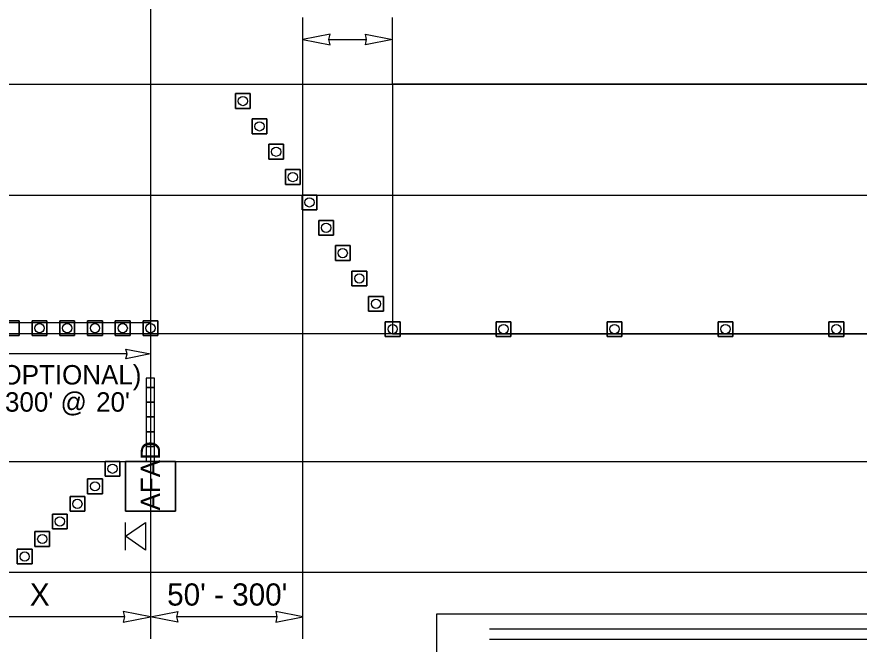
# Model space of a CAD drawing. Extents: x 99999.1 to 100095.7, y 99995 to 100010.7.
# Drawn here: x 100003.795 to 100006.832, y 100005.473 to 100007.734 of the extents above; entities that cross this region are included whole.
import ezdxf

# ---------------------------------------------------------------- set-up
doc = ezdxf.new("R2010")
doc.units = 0
for name, color, linetype in [('RD_ED_ShoulderPavedEdge', 7, 'Continuous'), ('RD_MK_LineDblYellowCenter', 7, 'Continuous'), ('RD_MK_LineEdgeWhite', 7, 'Continuous'), ('RD_MK_LineNoPass', 7, 'Continuous'), ('RD_MK_LineSkipCenter', 7, 'Continuous'), ('TR_WZ_AFAD', 7, 'Continuous'), ('TR_WZ_PortableSignMountBlk-Wht', 7, 'Continuous'), ('TR_WZ_TrafficCone', 7, 'Continuous'), ('TR_WZ_WorkZoneDetails', 7, 'Continuous'), ('TR_WZ_WorkZoneTextCurrent', 7, 'Continuous')]:
    doc.layers.add(name, color=color, linetype=linetype)

msp = doc.modelspace()

# ---------------------------------------------------------------- linework, layer by layer
at = {"layer": 'RD_ED_ShoulderPavedEdge'}
for p, q in [((100000.1076, 100007.4923), (100015.6424, 100007.4923)), ((100000.1076, 100005.7323), (100015.6424, 100005.7323))]:
    msp.add_line(p, q, dxfattribs=at)
at = {"layer": 'RD_MK_LineDblYellowCenter'}
for p, q in [((100005.4994, 100005.5286), (100008.0081, 100005.5286)), ((100005.4994, 100005.4911), (100008.0081, 100005.4911))]:
    msp.add_line(p, q, dxfattribs=at)
at = {"layer": 'RD_MK_LineEdgeWhite'}
for p, q in [((100000.1076, 100007.0923), (100015.6424, 100007.0923)), ((100000.1076, 100006.1323), (100015.6424, 100006.1323))]:
    msp.add_line(p, q, dxfattribs=at)
at = {"layer": 'RD_MK_LineNoPass'}
msp.add_line((100003.4767, 100006.6323), (100004.2767, 100006.6323), dxfattribs=at)
at = {"layer": 'RD_MK_LineSkipCenter'}
msp.add_lwpolyline([(100011.15, 100006.5923), (100003.4767, 100006.5923)], dxfattribs=at)
at = {"layer": 'TR_WZ_AFAD'}
for p, q in [((100004.2916, 100006.399), (100004.2916, 100006.4323)), ((100004.2616, 100006.399), (100004.2616, 100006.3457)), ((100004.2616, 100006.399), (100004.2766, 100006.399)), ((100004.2766, 100006.399), (100004.2916, 100006.399)), ((100004.2916, 100006.3457), (100004.2916, 100006.399)), ((100004.2616, 100006.3457), (100004.2616, 100006.2923)), ((100004.2766, 100006.3457), (100004.2616, 100006.3457)), ((100004.2916, 100006.3457), (100004.2766, 100006.3457)), ((100004.2916, 100006.2923), (100004.2916, 100006.3457)), ((100004.2616, 100006.2923), (100004.2616, 100006.239)), ((100004.2616, 100006.2923), (100004.2766, 100006.2923)), ((100004.2766, 100006.2923), (100004.2916, 100006.2923)), ((100004.2916, 100006.239), (100004.2916, 100006.2923)), ((100004.2766, 100006.239), (100004.2616, 100006.239)), ((100004.2616, 100006.239), (100004.2616, 100006.1857)), ((100004.2916, 100006.239), (100004.2766, 100006.239)), ((100004.2916, 100006.1857), (100004.2916, 100006.239)), ((100004.2616, 100006.1857), (100004.2616, 100006.1323)), ((100004.1866, 100005.9523), (100004.1866, 100006.1323)), ((100004.1866, 100006.1323), (100004.3666, 100006.1323)), ((100004.27, 100006.1323), (100004.1866, 100006.1323)), ((100004.1866, 100006.1323), (100004.1866, 100005.9523)), ((100004.2616, 100006.1323), (100004.27, 100006.1323)), ((100004.27, 100006.1323), (100004.2766, 100006.1323)), ((100004.3666, 100006.1323), (100004.3666, 100005.9523)), ((100004.3666, 100005.9523), (100004.3666, 100006.1323)), ((100004.3666, 100005.9523), (100004.1866, 100005.9523)), ((100004.1866, 100005.9523), (100004.3666, 100005.9523))]:
    msp.add_line(p, q, dxfattribs=at)
for points in [[(100004.2916, 100006.4323), (100004.2616, 100006.4323), (100004.2616, 100006.399)], [(100004.2916, 100006.1323), (100004.2916, 100006.4323), (100004.2616, 100006.4323), (100004.2616, 100006.1323)], [(100004.2916, 100006.399), (100004.2766, 100006.399), (100004.2616, 100006.399)], [(100004.2616, 100006.3457), (100004.2766, 100006.3457), (100004.2916, 100006.3457)], [(100004.2916, 100006.2923), (100004.2766, 100006.2923), (100004.2616, 100006.2923)], [(100004.2616, 100006.239), (100004.2766, 100006.239), (100004.2916, 100006.239)], [(100004.2916, 100006.1857), (100004.2766, 100006.1857), (100004.2616, 100006.1857)], [(100004.2616, 100006.1857), (100004.2766, 100006.1857), (100004.2916, 100006.1857)], [(100004.2766, 100006.1323), (100004.2833, 100006.1323), (100004.2916, 100006.1323), (100004.2916, 100006.1857)], [(100004.3666, 100006.1323), (100004.2833, 100006.1323), (100004.27, 100006.1323)]]:
    msp.add_lwpolyline(points, dxfattribs=at)
at = {"layer": 'TR_WZ_PortableSignMountBlk-Wht'}
msp.add_line((100004.1867, 100005.8123), (100004.1867, 100005.9123), dxfattribs=at)
msp.add_lwpolyline([(100004.1867, 100005.8622), (100004.2585, 100005.9123), (100004.2585, 100005.8123)], close=True, dxfattribs=at)
at = {"layer": 'TR_WZ_TrafficCone'}
for points in [[(100004.6367, 100007.4577), (100004.5834, 100007.4577), (100004.5834, 100007.4043), (100004.6367, 100007.4043), (100004.6367, 100007.4577)], [(100004.6367, 100007.4043), (100004.5834, 100007.4043), (100004.5834, 100007.4577), (100004.6367, 100007.4577), (100004.6367, 100007.4043)], [(100004.6967, 100007.3663), (100004.6434, 100007.3663), (100004.6434, 100007.313), (100004.6967, 100007.313), (100004.6967, 100007.3663)], [(100004.6967, 100007.313), (100004.6434, 100007.313), (100004.6434, 100007.3663), (100004.6967, 100007.3663), (100004.6967, 100007.313)], [(100004.7567, 100007.275), (100004.7034, 100007.275), (100004.7034, 100007.2217), (100004.7567, 100007.2217), (100004.7567, 100007.275)], [(100004.7567, 100007.2217), (100004.7034, 100007.2217), (100004.7034, 100007.275), (100004.7567, 100007.275), (100004.7567, 100007.2217)], [(100004.8167, 100007.1837), (100004.7634, 100007.1837), (100004.7634, 100007.1303), (100004.8167, 100007.1303), (100004.8167, 100007.1837)], [(100004.8167, 100007.1303), (100004.7634, 100007.1303), (100004.7634, 100007.1837), (100004.8167, 100007.1837), (100004.8167, 100007.1303)], [(100004.8234, 100007.0923), (100004.8767, 100007.0923), (100004.8767, 100007.039), (100004.8234, 100007.039), (100004.8234, 100007.0923)], [(100004.8234, 100007.039), (100004.8767, 100007.039), (100004.8767, 100007.0923), (100004.8234, 100007.0923), (100004.8234, 100007.039)], [(100004.8834, 100007.001), (100004.9367, 100007.001), (100004.9367, 100006.9477), (100004.8834, 100006.9477), (100004.8834, 100007.001)], [(100004.8834, 100006.9477), (100004.9367, 100006.9477), (100004.9367, 100007.001), (100004.8834, 100007.001), (100004.8834, 100006.9477)], [(100004.9434, 100006.9097), (100004.9967, 100006.9097), (100004.9967, 100006.8563), (100004.9434, 100006.8563), (100004.9434, 100006.9097)], [(100004.9434, 100006.8563), (100004.9967, 100006.8563), (100004.9967, 100006.9097), (100004.9434, 100006.9097), (100004.9434, 100006.8563)], [(100005.0034, 100006.8183), (100005.0567, 100006.8183), (100005.0567, 100006.765), (100005.0034, 100006.765), (100005.0034, 100006.8183)], [(100005.0034, 100006.765), (100005.0567, 100006.765), (100005.0567, 100006.8183), (100005.0034, 100006.8183), (100005.0034, 100006.765)], [(100005.0634, 100006.727), (100005.1167, 100006.727), (100005.1167, 100006.6737), (100005.0634, 100006.6737), (100005.0634, 100006.727)], [(100005.0634, 100006.6737), (100005.1167, 100006.6737), (100005.1167, 100006.727), (100005.0634, 100006.727), (100005.0634, 100006.6737)], [(100003.8033, 100006.639), (100003.75, 100006.639), (100003.75, 100006.5857), (100003.8033, 100006.5857), (100003.8033, 100006.639)], [(100003.8033, 100006.5857), (100003.75, 100006.5857), (100003.75, 100006.639), (100003.8033, 100006.639), (100003.8033, 100006.5857)], [(100003.9033, 100006.639), (100003.85, 100006.639), (100003.85, 100006.5857), (100003.9033, 100006.5857), (100003.9033, 100006.639)], [(100003.9033, 100006.5857), (100003.85, 100006.5857), (100003.85, 100006.639), (100003.9033, 100006.639), (100003.9033, 100006.5857)], [(100004.0033, 100006.639), (100003.95, 100006.639), (100003.95, 100006.5857), (100004.0033, 100006.5857), (100004.0033, 100006.639)], [(100004.0033, 100006.5857), (100003.95, 100006.5857), (100003.95, 100006.639), (100004.0033, 100006.639), (100004.0033, 100006.5857)], [(100004.1033, 100006.639), (100004.05, 100006.639), (100004.05, 100006.5857), (100004.1033, 100006.5857), (100004.1033, 100006.639)], [(100004.1033, 100006.5857), (100004.05, 100006.5857), (100004.05, 100006.639), (100004.1033, 100006.639), (100004.1033, 100006.5857)], [(100004.2033, 100006.639), (100004.15, 100006.639), (100004.15, 100006.5857), (100004.2033, 100006.5857), (100004.2033, 100006.639)], [(100004.2033, 100006.5857), (100004.15, 100006.5857), (100004.15, 100006.639), (100004.2033, 100006.639), (100004.2033, 100006.5857)], [(100004.3033, 100006.639), (100004.25, 100006.639), (100004.25, 100006.5857), (100004.3033, 100006.5857), (100004.3033, 100006.639)], [(100004.3033, 100006.5857), (100004.25, 100006.5857), (100004.25, 100006.639), (100004.3033, 100006.639), (100004.3033, 100006.5857)], [(100005.1234, 100006.6357), (100005.1767, 100006.6357), (100005.1767, 100006.5823), (100005.1234, 100006.5823), (100005.1234, 100006.6357)], [(100005.1234, 100006.5823), (100005.1767, 100006.5823), (100005.1767, 100006.6357), (100005.1234, 100006.6357), (100005.1234, 100006.5823)], [(100005.5234, 100006.6357), (100005.5767, 100006.6357), (100005.5767, 100006.5823), (100005.5234, 100006.5823), (100005.5234, 100006.6357)], [(100005.5234, 100006.5823), (100005.5767, 100006.5823), (100005.5767, 100006.6357), (100005.5234, 100006.6357), (100005.5234, 100006.5823)], [(100005.9234, 100006.6357), (100005.9767, 100006.6357), (100005.9767, 100006.5823), (100005.9234, 100006.5823), (100005.9234, 100006.6357)], [(100005.9234, 100006.5823), (100005.9767, 100006.5823), (100005.9767, 100006.6357), (100005.9234, 100006.6357), (100005.9234, 100006.5823)], [(100006.3234, 100006.6357), (100006.3767, 100006.6357), (100006.3767, 100006.5823), (100006.3234, 100006.5823), (100006.3234, 100006.6357)], [(100006.3234, 100006.5823), (100006.3767, 100006.5823), (100006.3767, 100006.6357), (100006.3234, 100006.6357), (100006.3234, 100006.5823)], [(100006.7234, 100006.6357), (100006.7767, 100006.6357), (100006.7767, 100006.5823), (100006.7234, 100006.5823), (100006.7234, 100006.6357)], [(100006.7234, 100006.5823), (100006.7767, 100006.5823), (100006.7767, 100006.6357), (100006.7234, 100006.6357), (100006.7234, 100006.5823)], [(100004.1133, 100006.1323), (100004.1667, 100006.1323), (100004.1667, 100006.079), (100004.1133, 100006.079), (100004.1133, 100006.1323)], [(100004.1133, 100006.079), (100004.1667, 100006.079), (100004.1667, 100006.1323), (100004.1133, 100006.1323), (100004.1133, 100006.079)], [(100004.05, 100006.069), (100004.1033, 100006.069), (100004.1033, 100006.0157), (100004.05, 100006.0157), (100004.05, 100006.069)], [(100004.05, 100006.0157), (100004.1033, 100006.0157), (100004.1033, 100006.069), (100004.05, 100006.069), (100004.05, 100006.0157)], [(100003.9867, 100006.0057), (100004.04, 100006.0057), (100004.04, 100005.9523), (100003.9867, 100005.9523), (100003.9867, 100006.0057)], [(100003.9867, 100005.9523), (100004.04, 100005.9523), (100004.04, 100006.0057), (100003.9867, 100006.0057), (100003.9867, 100005.9523)], [(100003.9767, 100005.9423), (100003.9233, 100005.9423), (100003.9233, 100005.889), (100003.9767, 100005.889), (100003.9767, 100005.9423)], [(100003.9767, 100005.889), (100003.9233, 100005.889), (100003.9233, 100005.9423), (100003.9767, 100005.9423), (100003.9767, 100005.889)], [(100003.9133, 100005.879), (100003.86, 100005.879), (100003.86, 100005.8257), (100003.9133, 100005.8257), (100003.9133, 100005.879)], [(100003.9133, 100005.8257), (100003.86, 100005.8257), (100003.86, 100005.879), (100003.9133, 100005.879), (100003.9133, 100005.8257)], [(100003.85, 100005.8157), (100003.7967, 100005.8157), (100003.7967, 100005.7623), (100003.85, 100005.7623), (100003.85, 100005.8157)], [(100003.85, 100005.7623), (100003.7967, 100005.7623), (100003.7967, 100005.8157), (100003.85, 100005.8157), (100003.85, 100005.7623)]]:
    msp.add_lwpolyline(points, dxfattribs=at)
for centre in [(100004.61, 100007.431), (100004.67, 100007.3397), (100004.73, 100007.2483), (100004.79, 100007.157), (100004.85, 100007.0657), (100004.91, 100006.9743), (100004.97, 100006.883), (100005.03, 100006.7917), (100005.09, 100006.7003), (100003.8767, 100006.6123), (100003.9767, 100006.6123), (100004.0767, 100006.6123), (100004.1767, 100006.6123), (100004.2767, 100006.6123), (100005.15, 100006.609), (100005.55, 100006.609), (100005.95, 100006.609), (100006.35, 100006.609), (100006.75, 100006.609), (100004.14, 100006.1057), (100004.0767, 100006.0423), (100004.0133, 100005.979), (100003.95, 100005.9157), (100003.8867, 100005.8523), (100003.8233, 100005.789)]:
    msp.add_circle(centre, 0.0167, dxfattribs=at)
at = {"layer": 'TR_WZ_WorkZoneDetails'}
for p, q in [((100004.2767, 100008.7991), (100004.2767, 100005.4923)), ((100004.8267, 100005.4923), (100004.8267, 100007.7323)), ((100005.15, 100007.4923), (100005.15, 100007.7323)), ((100004.9204, 100007.6523), (100005.0563, 100007.6523)), ((100004.1923, 100006.5193), (100003.761, 100006.5193)), ((100004.1829, 100005.5723), (100003.5704, 100005.5723)), ((100004.7329, 100005.5723), (100004.3704, 100005.5723))]:
    msp.add_line(p, q, dxfattribs=at)
for points in [[(100004.8267, 100007.6523), (100004.9249, 100007.6331), (100004.9204, 100007.6523), (100004.9249, 100007.6716)], [(100005.15, 100007.6523), (100005.0517, 100007.6331), (100005.0563, 100007.6523), (100005.0517, 100007.6716)], [(100005.15, 100007.4923), (100005.15, 100006.5923), (100009.9338, 100006.5923), (100009.9338, 100007.4923)], [(100004.2767, 100006.5193), (100004.1882, 100006.502), (100004.1923, 100006.5193), (100004.1882, 100006.5367)], [(100004.2767, 100005.5723), (100004.1784, 100005.5916), (100004.1829, 100005.5723), (100004.1784, 100005.5531)], [(100004.2767, 100005.5723), (100004.3749, 100005.5916), (100004.3704, 100005.5723), (100004.3749, 100005.5531)], [(100004.8267, 100005.5723), (100004.7284, 100005.5916), (100004.7329, 100005.5723), (100004.7284, 100005.5531)]]:
    msp.add_lwpolyline(points, close=True, dxfattribs=at)
at = {"layer": 'TR_WZ_WorkZoneTextCurrent'}
msp.add_lwpolyline([(100005.3092, 100005.5823), (100009.1102, 100005.5823), (100009.1102, 100003.4799), (100005.3092, 100003.4799)], close=True, dxfattribs=at)

# ---------------------------------------------------------------- texts
at = {"layer": 'TR_WZ_AFAD'}
msp.add_text('AFAD', height=0.07, rotation=90, dxfattribs=at).set_placement((100004.3116, 100005.9553))
at = {"layer": 'TR_WZ_WorkZoneTextCurrent'}
for s, p in [('(OPTIONAL)', (100003.7085, 100006.4093)), ("300' @", (100003.7523, 100006.3113)), ("20'", (100004.0807, 100006.3113))]:
    msp.add_text(s, height=0.07, dxfattribs=at).set_placement(p)
for s, p in [('X', (100003.8419, 100005.6123)), ("50' - 300'", (100004.3369, 100005.6123))]:
    msp.add_text(s, height=0.08, rotation=360, dxfattribs=at).set_placement(p)

doc.saveas('drawing.dxf')
